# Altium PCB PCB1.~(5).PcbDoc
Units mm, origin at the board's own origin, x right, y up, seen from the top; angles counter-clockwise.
Board outline 127 x 101.6 mm, 3 copper layers (Top Layer, Internal Plane 1, Bottom Layer); 15 components, 13 nets, 51 pads, 0 vias.
Unrouted connection lines stored in the file: 2.
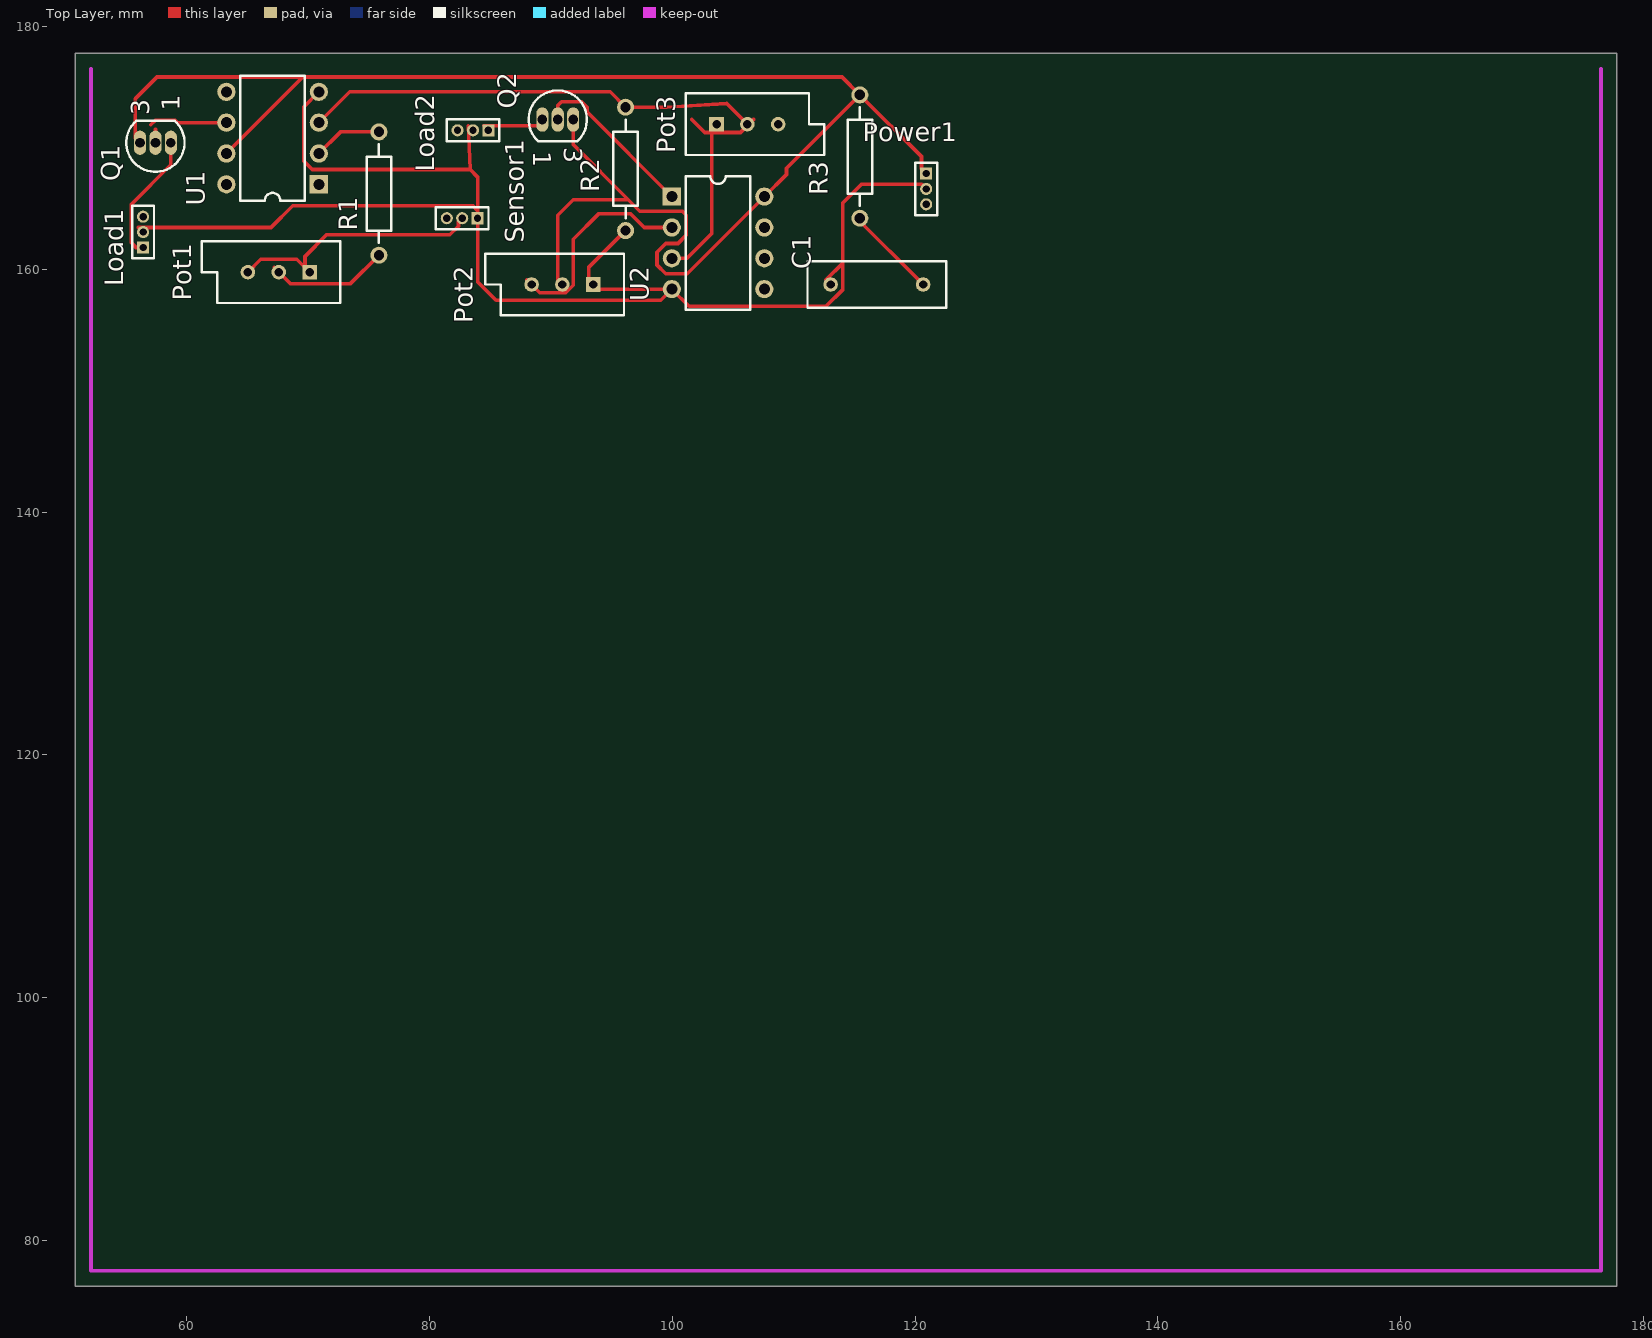
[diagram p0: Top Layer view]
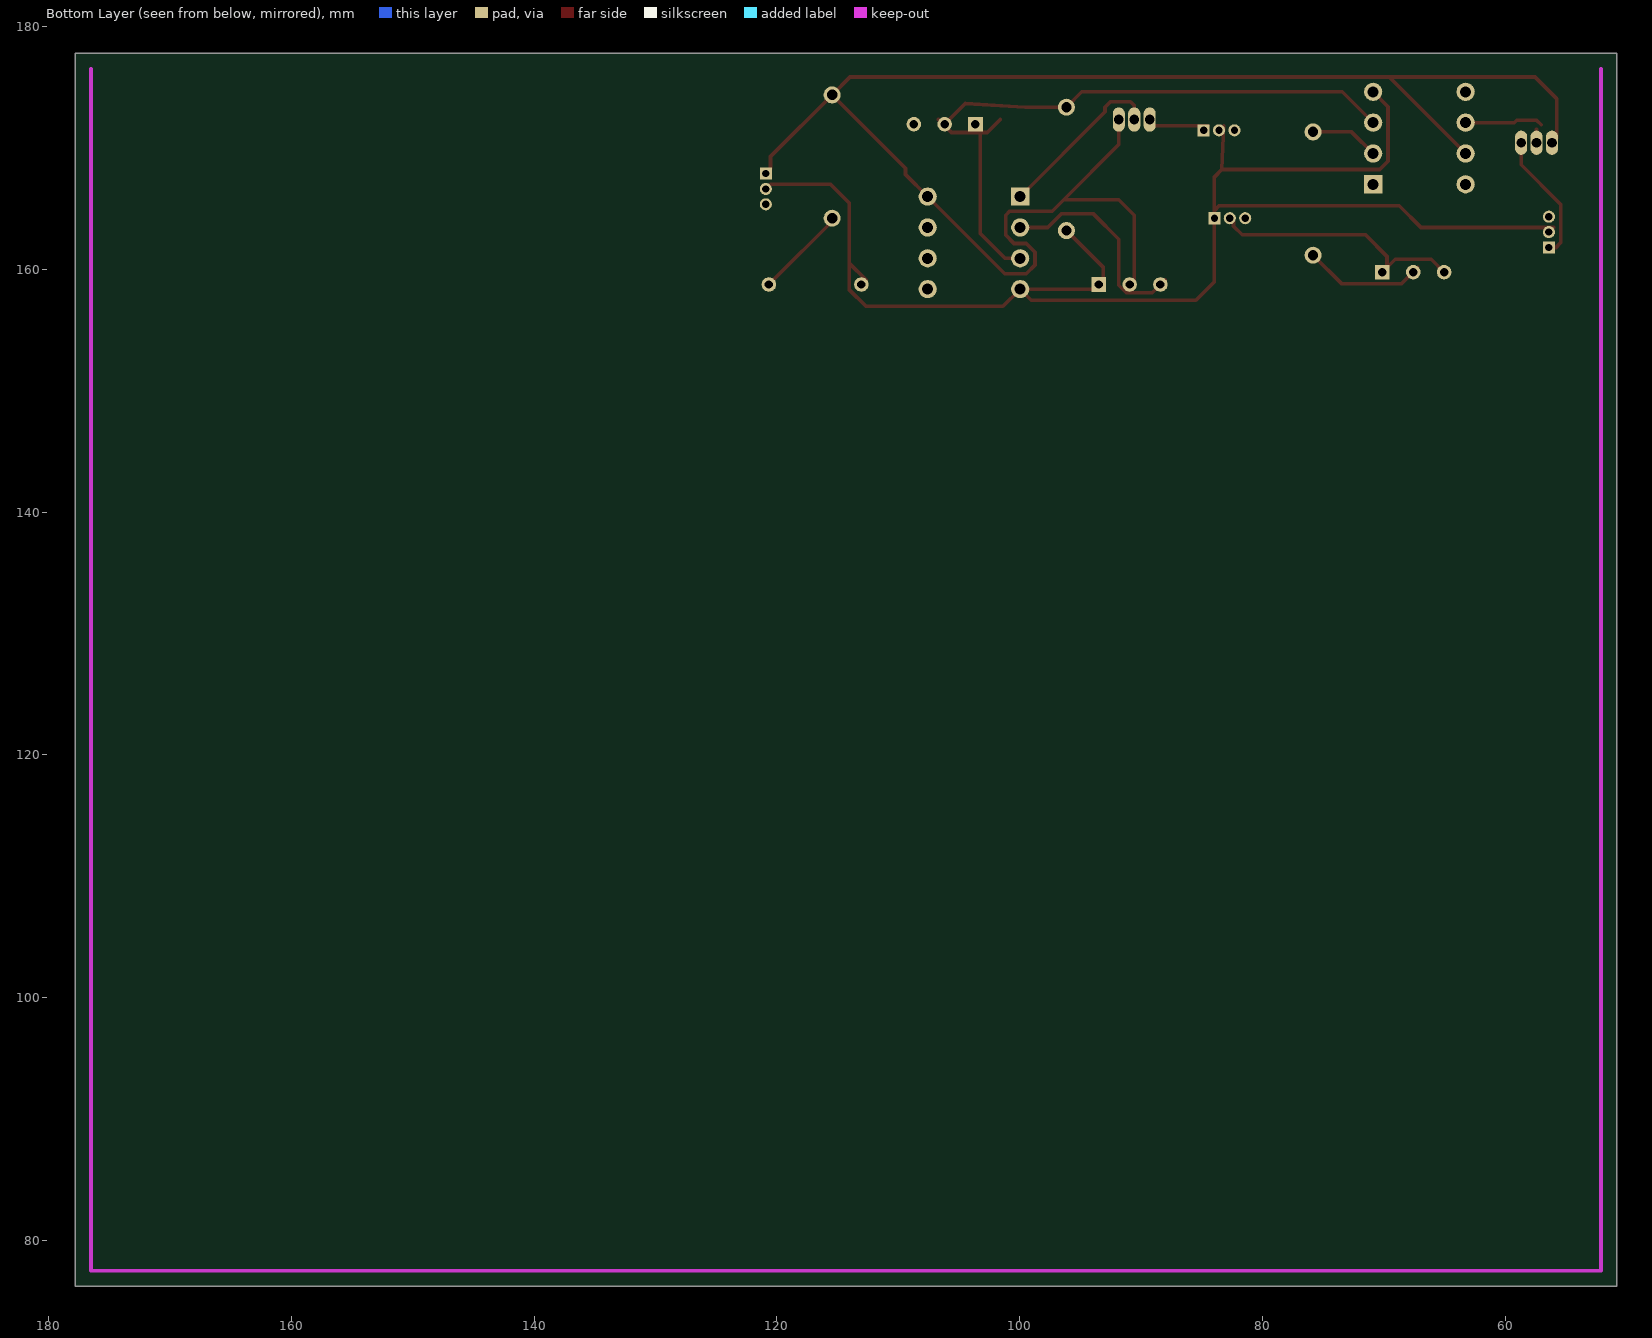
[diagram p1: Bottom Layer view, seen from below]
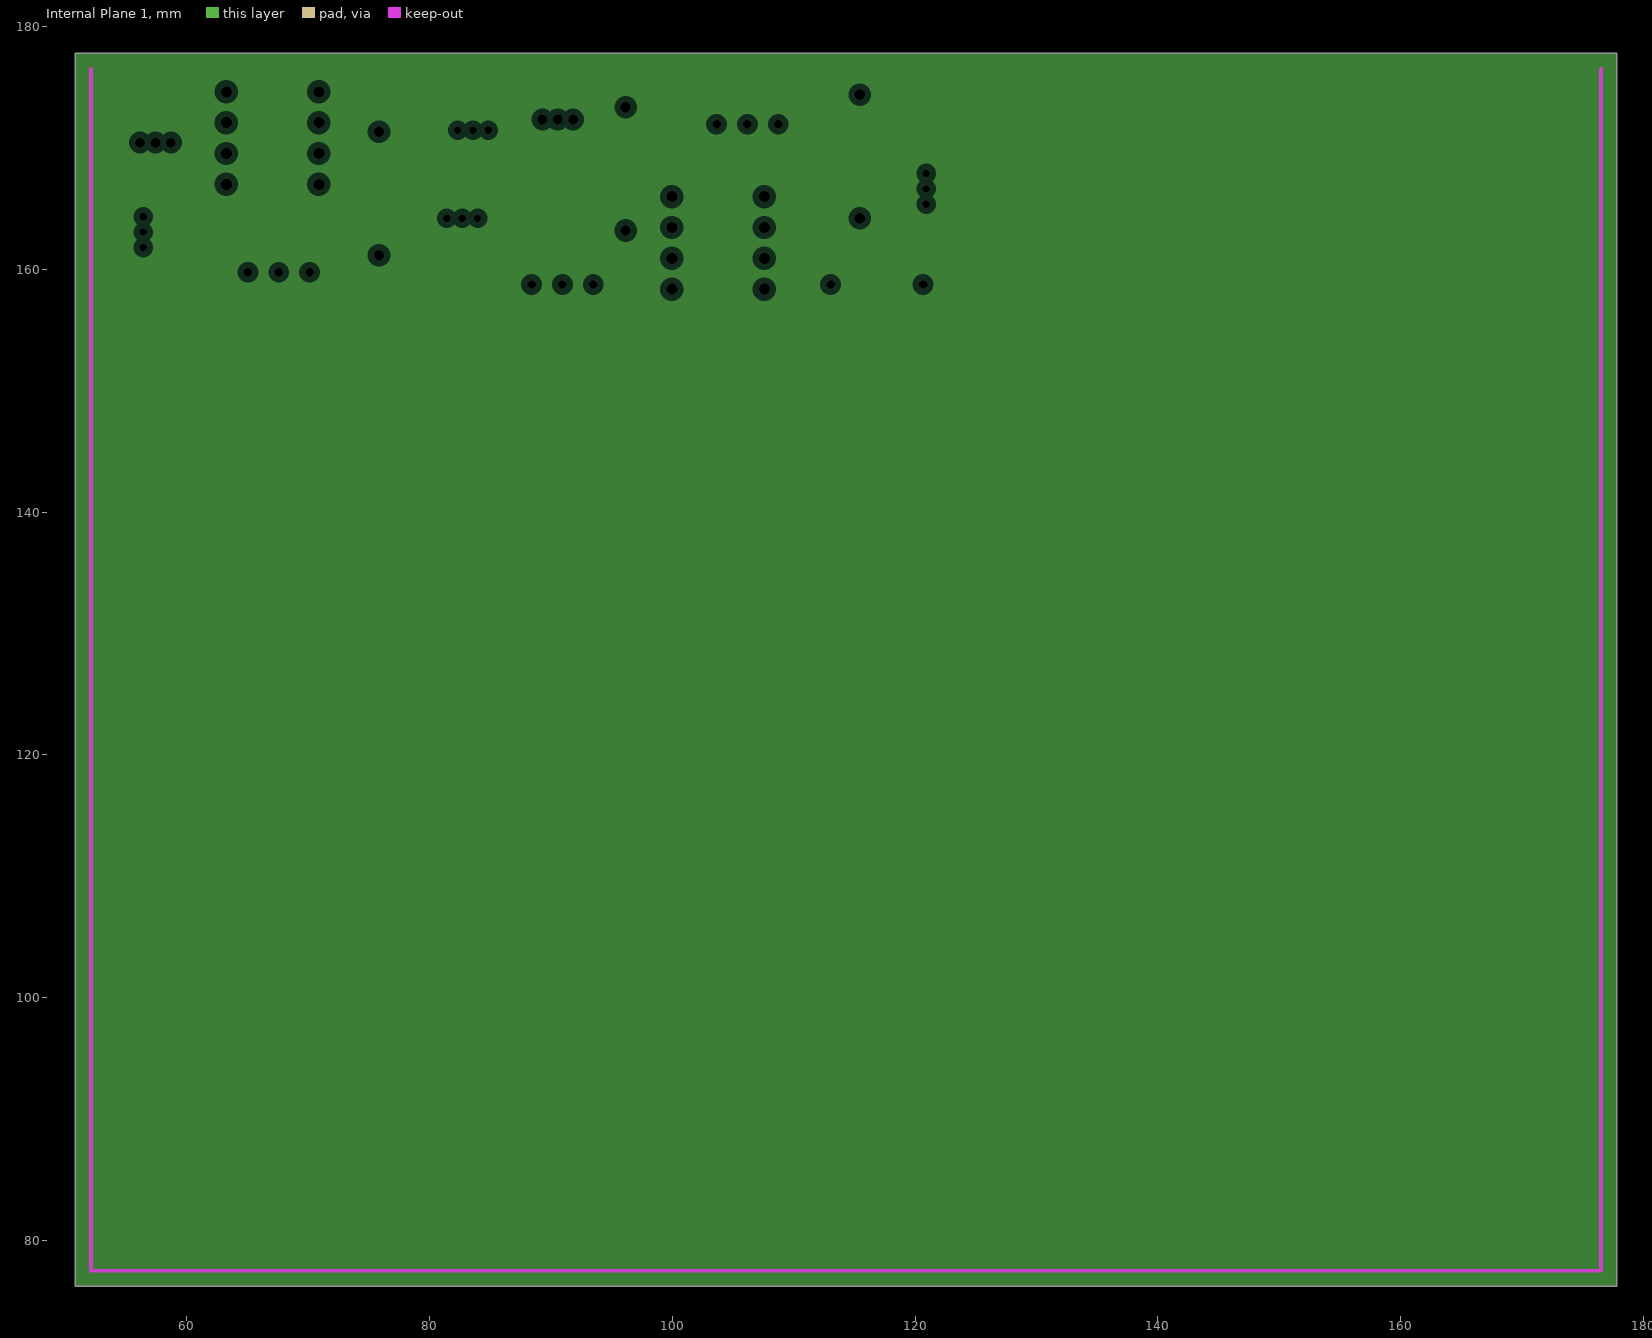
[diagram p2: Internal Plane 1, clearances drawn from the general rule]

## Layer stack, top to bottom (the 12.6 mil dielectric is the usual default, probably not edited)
Top Layer: signal copper 0.0356
Dielectric: dielectric 0.32, FR-4, Dk 4.8
Internal Plane 1: plane copper 0.0356
Dielectric: dielectric 0.32, FR-4, Dk 4.8
Bottom Layer: signal copper 0.0356

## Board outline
50.8,76.2 177.8,76.2 177.8,177.8 50.8,177.8

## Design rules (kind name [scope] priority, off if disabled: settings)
Clearance [All] p1: gap=0.3
ComponentClearance [All] p1: gap=0.254 collisioncheckmode=3 verticalgap=0.254
PlaneClearance [All] p1: clearance=0.508
PlaneConnect [All] p1: planeconnectstyle=Relief reliefexpansion=0.508 reliefentries=4 reliefconductorwidth=0.254 reliefairgap=0.254
PolygonConnect [All] p1: connectstyle=Relief reliefconductorwidth=0.254 reliefentries=4 polygonreliefangle="90 Angle"
RoomDefinition Sheet1 [InComponentClass('Sheet1')] p1: confinementstyle=ConfineIn formatcopy=TRUE lockcomponents=FALSE outline 52.324,154.559 124.46,154.559 124.46,177.038 52.324,177.038
RoutingVias [All] p1: holewidth=0.8 width=1.6 viastyle="Through Hole" minholewidth=0.711 minwidth=1.27 maxholewidth=0.711 maxwidth=1.27
SolderMaskExpansion [All] p1: expansion=0.102
TestPointUsage [All] p1: valid=0 allowmultiple=FALSE
Testpoint [All] p1: side=15 testpointundercomponent=TRUE minsize=1.016 maxsize=2.54 preferedsize=1.524 minholesize=0 maxholesize=1.016 preferedholesize=0.813 testpointgrid=0.025 style=1023 order=0-112345678
Width [All] p1: maxlimit=0.3 minlimit=0.3 preferedwidth=0.3
16 further rules are at their usual default settings.

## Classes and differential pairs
component class Sheet1: Q2 R1 R2 R3 Sensor1 U1 U2

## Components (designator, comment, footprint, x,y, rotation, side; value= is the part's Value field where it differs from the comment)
C1 "Cap" RAD-0.3 116.84,158.75 r0 top
Load1 "MHDR1X3" MHDR1X3 56.388,161.798 r90 top
Load2 "MHDR1X3" MHDR1X3 84.836,171.45 r180 top
Pot1 "RPot" VR5 67.564,159.766 r180 top
Pot2 "RPot" VR5 90.932,158.75 r180 top (schematic designator Pot3)
Pot3 "RPot" VR5 106.172,171.958 r0 top (schematic designator Pot2)
Power1 "MHDR1X3" MHDR1X3 120.904,167.894 r270 top (schematic designator Power)
Q1 "BC547A" SOT54 57.404,170.434 r90 top
Q2 "BC547A" SOT54 90.551,172.339 r270 top
R1 "Res2" AXIAL-0.4 75.819,166.243 r90 top
R2 "Res2" AXIAL-0.4 96.139,168.275 r90 top
R3 "Res2" AXIAL-0.4 115.443,169.291 r90 top
Sensor1 "MHDR1X3" MHDR1X3 83.947,164.211 r180 top (schematic designator Sensor)
U1 "LM741J/883" N08E 67.056,170.815 r90 top
U2 "LM393P" P008 103.759,162.179 r270 top

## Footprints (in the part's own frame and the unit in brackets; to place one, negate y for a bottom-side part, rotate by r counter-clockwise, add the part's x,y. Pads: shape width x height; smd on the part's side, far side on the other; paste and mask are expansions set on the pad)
AXIAL-0.4 [mm] "Resistor; 2 Leads"
  round 1.4 hole 0.85: 1(-5.08,0) 2(5.08,0)
  silkscreen extent -4.06,-1.02 4.06,1.02
MHDR1X3 [mm] "Connector; Header; 3 Position"
  rect 1x1 hole 0.6: 1(0,0)
  round 1 hole 0.6: 2(1.27,0) 3(2.54,0)
  silkscreen extent -0.9,-0.9 3.44,0.9
N08E [mm] "DIP; 8 Leads; Row Spacing 7.62 mm; Pitch 2.54 mm"
  rect 1.5x1.5 hole 0.9: 1(-3.81,-3.81)
  round 1.5 hole 0.9: 2(-1.27,-3.81) 3(1.27,-3.81) 4(3.81,-3.81) 5(3.81,3.81) 6(1.27,3.81) 7(-1.27,3.81) 8(-3.81,3.81)
  silkscreen extent -5.15,-2.65 5.15,2.65
P008 [mm] "DIP; 8 Leads; Row Spacing 7.62 mm; Pitch 2.54 mm"
  rect 1.5x1.5 hole 0.9: 1(-3.81,-3.81)
  round 1.5 hole 0.9: 2(-1.27,-3.81) 3(1.27,-3.81) 4(3.81,-3.81) 5(3.81,3.81) 6(1.27,3.81) 7(-1.27,3.81) 8(-3.81,3.81)
  silkscreen extent -5.5,-2.65 5.5,2.65
RAD-0.3 [mm] "Capacitor; 2 Leads"
  round 1.2 hole 0.7: 1(-3.81,0) 2(3.81,0)
  silkscreen extent -5.71,-1.91 5.71,1.91
SOT54 [mm] "TO, Flat Index; 3 In-Line, Axial Leads; Body Dia. 4.6mm; Leads 0.48 x 0.45 mm (max)"
  oval 2x1 hole 0.8: 1(0,-1.27) 2(0,0) 3(0,1.27)
  silkscreen extent -2.4,-2.4 1.8,2.4
VR5 [mm] "Potentiometer; 3 Leads"
  rect 1.2x1.2 hole 0.7: 1(-2.54,0)
  round 1.2 hole 0.7: 2(0,0) 3(2.54,0)
  silkscreen extent -5.08,-2.54 6.35,2.54

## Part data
C1: "Capacitor"
Load1 Load2 Power1 Sensor1: "Header, 3-Pin"
Pot1 Pot2 Pot3: "Potentiometer"
Q1 Q2: "NPN General-purpose Transistor"
R1 R2 R3: "Resistor"
U1: "Operational Amplifier"
U2: "Dual Differential Comparator"

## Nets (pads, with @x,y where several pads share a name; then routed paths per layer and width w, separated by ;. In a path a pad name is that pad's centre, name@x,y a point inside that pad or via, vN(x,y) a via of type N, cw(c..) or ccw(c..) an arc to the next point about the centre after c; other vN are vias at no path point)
GND: C1.1 Load1.2 Load2.2 Pot2.1 Power1.2 R2.1 Sensor1.1 U1.4 U2.4 | length 123.1
  Top Layer w0.3: 56.007,163.449 66.929,163.449 68.707,165.227 83.566,165.227 83.947,164.846 ; U1.4 69.647,173.406 69.647,168.91 70.333,168.224 83.337,168.224 ; 83.185,171.831 83.337,168.224 ; R2.1 93.091,160.147 93.091,159.131 93.853,158.369 U2.4 ; C1.1@112.649,159.131 114.046,160.528 ; 120.523,167.005 115.57,167.005 114.046,165.481 114.046,160.528 ; 83.337,168.224 83.947,167.615 83.947,164.846 ; 83.947,164.846 Sensor1.1 83.947,158.979 85.471,157.455 99.035,157.455 U2.4 ; U2.4 101.371,156.947 112.649,156.947 114.046,158.344 114.046,160.528
NetC1_2: C1.2 R3.1 | length 7.1
  Top Layer w0.3: R3.1 115.443,163.957 C1.2@120.269,159.131
NetLoad1_1: Load1.1 Q1.1 | length 10.7
  Top Layer w0.3: Load1.1 55.804,161.798 55.423,162.179 55.423,165.354 58.674,168.605 Q1.1
NetLoad2_1: Load2.1 Q2.1 | length 5.3
  Top Layer w0.3: Load2.1@84.455,171.831 89.281,171.831 Q2.1
NetPot1_1: Pot1.1 Pot1.3 Sensor1.2 | length 21.3
  Top Layer w0.3: Pot1.3 66.091,160.833 69.037,160.833 Pot1.1 ; Pot1.1@69.723,160.147 69.723,161.061 71.501,162.839 81.661,162.839 82.372,163.551 82.372,163.906 Sensor1.2
NetPot1_2: Pot1.2 R1.1 | length 10.2
  Top Layer w0.3: Pot1.2@67.183,160.147 68.504,158.826 73.482,158.826 R1.1
NetPot2_1: Pot3.1 Pot3.3 U2.3 | length 19.5
  Top Layer w0.3: U2.3 101.195,160.909 103.251,162.965 Pot3.1@103.251,172.339 ; 101.6,172.339 102.667,171.272 105.613,171.272 106.68,172.339
NetPot2_2: Pot3.2 R2.2 U1.3 | length 37.1
  Top Layer w0.3: U1.3 73.406,174.625 94.869,174.625 R2.2 99.543,173.355 104.47,173.66 Pot3.2@105.791,172.339
NetPot3_3: Pot2.3 U2.2 | length 17.8
  Top Layer w0.3: Pot2.3@88.011,159.131 89.078,158.064 91.186,158.064 91.821,158.699 91.821,162.484 93.904,164.567 96.571,164.567 97.689,163.449 U2.2
NetQ1_2: Q1.2 U1.6 | length 7.6
  Top Layer w0.3: 57.023,171.907 57.404,172.288 59.03,172.288 59.233,172.085 U1.6 ; Q1.2 57.404,171.526
NetQ2_2: Q2.2 U2.1 | length 14.1
  Top Layer w0.3: Q2.2 90.551,173.495 90.868,173.812 92.507,173.812 92.964,173.355 92.964,172.974 U2.1
NetR1_2: R1.2 U1.2 | length 5.7
  Top Layer w0.3: U1.2 72.644,171.323 R1.2
VCC: Pot2.2 Power1.1 Q1.3 Q2.3 R3.2 U1.7 U2.8 | length 136
  Top Layer w0.3: Q1.3@55.753,170.815 55.753,174.066 57.531,175.844 69.545,175.844 ; U1.7 69.545,175.844 ; Pot2.2@90.551,159.131 90.551,164.465 91.821,165.735 96.368,165.735 ; Q2.3 91.821,170.282 96.368,165.735 ; Power1.1@120.523,168.275 120.523,169.291 R3.2 ; 69.545,175.844 113.97,175.844 R3.2 ; 96.368,165.735 97.314,164.789 100.825,164.789 101.149,164.465 101.149,162.82 100.457,162.128 99.441,162.128 98.73,161.417 98.73,160.35 99.441,159.639 101.219,159.639 U2.8 109.398,167.818 109.398,168.326 R3.2
pads on no net: Load1.3 Load2.3 Power1.3 Sensor1.3 U1.1 U1.5 U1.8 U2.5 U2.6 U2.7

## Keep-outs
Keep-Out Layer:
  lines w0.3: 52.1,176.5 52.1,77.5 176.5,77.5 176.5,176.5

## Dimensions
52.1,77.5 to 176.5,77.5 on Mechanical 1
52.1,77.5 to 52.1,176.5 on Mechanical 1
